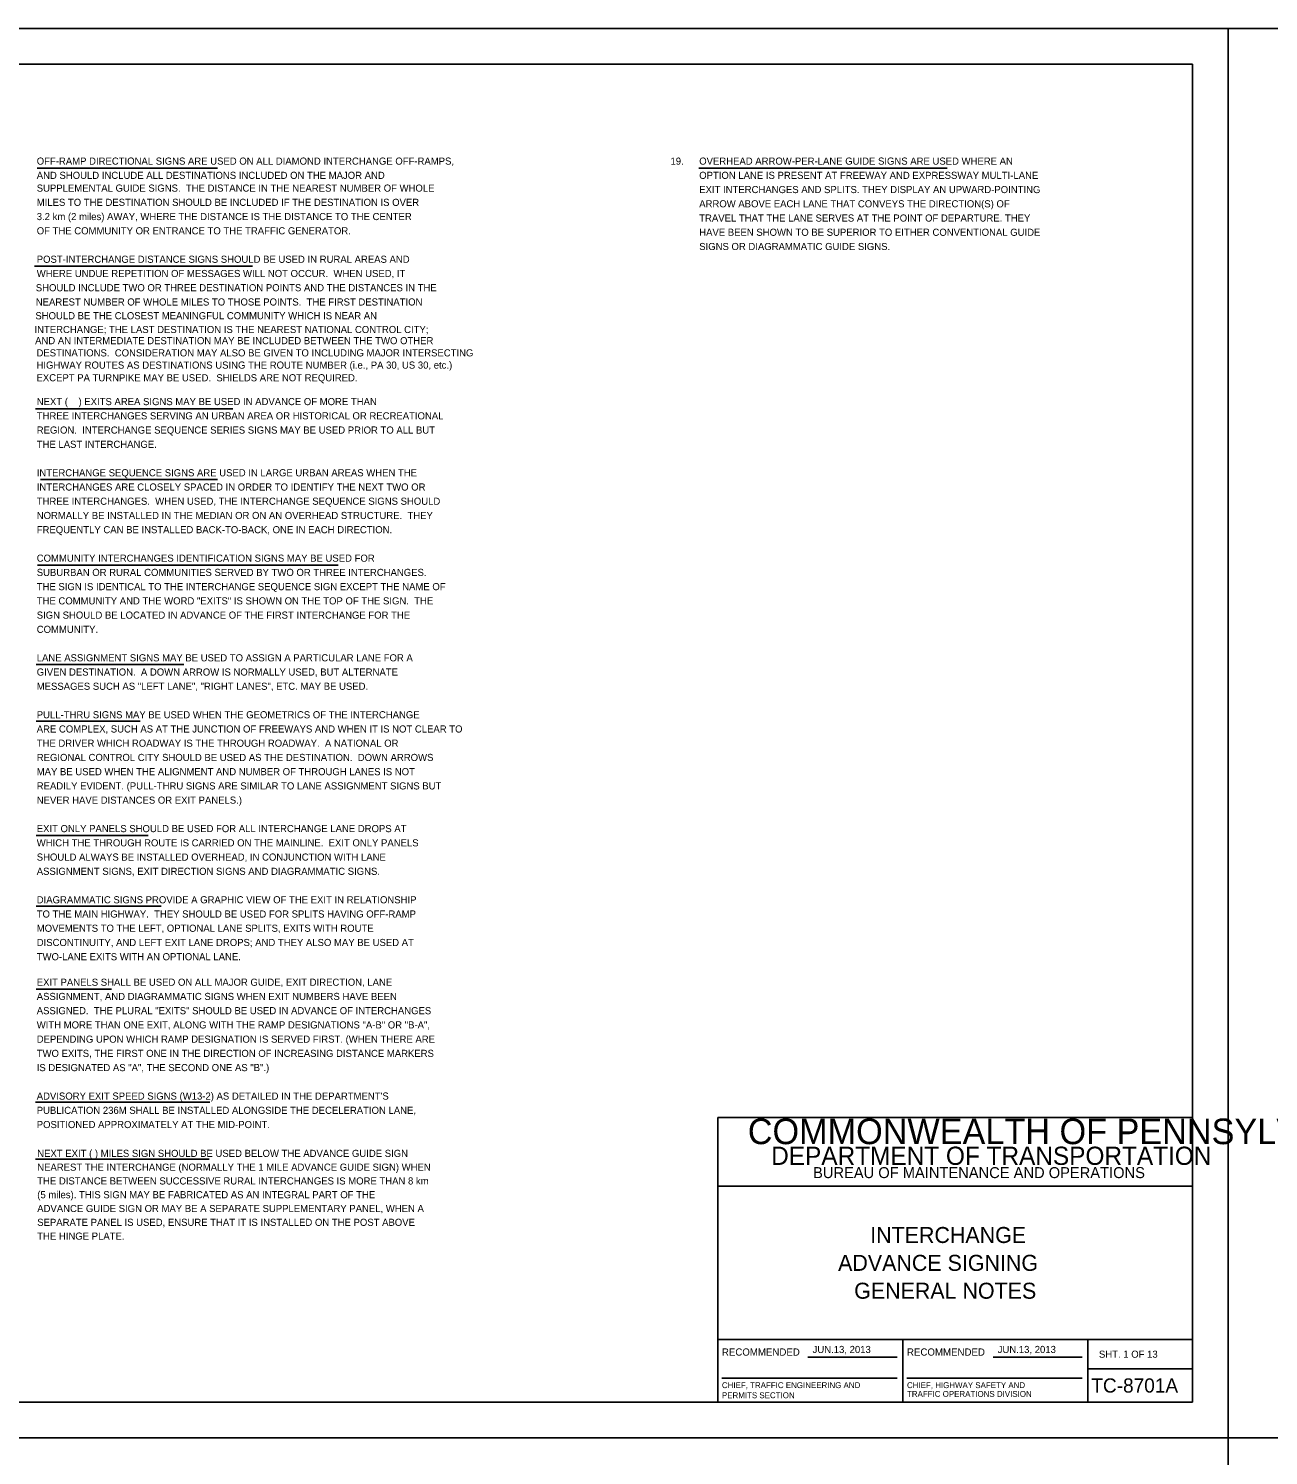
# Model space of a CAD drawing. Extents: x 644898 to 648326, y 298294 to 300670.
# Drawn here: x 645234 to 645756, y 300069 to 300670 of the extents above; entities that cross this region are included whole.
import ezdxf

# ---------------------------------------------------------------- set-up
doc = ezdxf.new("R2010")
doc.units = 0
for name, color, linetype in [('1', 7, 'Continuous'), ('2', 7, 'Continuous'), ('XCS-GRID-MIN', 7, 'Continuous')]:
    doc.layers.add(name, color=color, linetype=linetype)

msp = doc.modelspace()

# ---------------------------------------------------------------- linework, layer by layer
at = {"layer": '1'}
for p, q in [((644938.32, 300655.49), (645724.32, 300655.49)), ((645724.32, 300091.49), (645724.32, 300655.49)), ((645524.32, 300091.49), (645524.32, 300211.49)), ((645524.32, 300211.49), (645724.32, 300211.49)), ((645724.32, 300182.49), (645524.32, 300182.49)), ((645524.32, 300117.87), (645724.32, 300117.87)), ((645602.32, 300117.87), (645602.32, 300091.49)), ((645680.2, 300091.49), (645680.2, 300117.87)), ((645562.26, 300110.44), (645599.88, 300110.44)), ((645640.26, 300110.44), (645677.88, 300110.44)), ((645526.01, 300101.54), (645599.88, 300101.54)), ((645604.01, 300101.54), (645677.88, 300101.54)), ((645680.2, 300105.49), (645724.32, 300105.49)), ((645724.32, 300091.49), (644938.32, 300091.49)), ((644938.32, 300091.49), (645524.32, 300091.49))]:
    msp.add_line(p, q, dxfattribs=at)
at = {"layer": '2'}
for p, q in [((645237.5, 300611.62), (645313.5, 300611.62)), ((645516.22, 300611.63), (645620.93, 300611.63)), ((645236.37, 300570.37), (645328.25, 300570.37)), ((645236.75, 300510.24), (645319.87, 300510.24)), ((645238.87, 300480.37), (645313.5, 300480.37)), ((645237.62, 300444.24), (645364.25, 300444.24)), ((645237, 300402.37), (645299.25, 300402.37)), ((645237, 300378.49), (645280.87, 300378.49)), ((645237, 300330.37), (645284.25, 300330.37)), ((645237, 300300.49), (645289.62, 300300.49)), ((645237, 300265.62), (645268.75, 300265.62)), ((645236.75, 300217.87), (645310.25, 300217.87)), ((645236.75, 300193.87), (645309.88, 300193.87))]:
    msp.add_line(p, q, dxfattribs=at)
at = {"layer": 'XCS-GRID-MIN'}
for points in [[(644898.32, 300670.49), (645739.32, 300670.49), (645739.32, 300076.49), (644898.32, 300076.49)], [(645739.32, 300670.49), (646580.32, 300670.49), (646580.32, 300076.49), (645739.32, 300076.49)], [(644898.32, 300076.49), (645739.32, 300076.49), (645739.32, 299482.49), (644898.32, 299482.49)], [(645739.32, 300076.49), (646580.32, 300076.49), (646580.32, 299482.49), (645739.32, 299482.49)]]:
    msp.add_lwpolyline(points, close=True, dxfattribs=at)

# ---------------------------------------------------------------- texts
at = {"layer": '1'}
for s, height, p in [('COMMONWEALTH OF PENNSYLVANIA', 10.7828, (645536.92, 300200.22)), ('DEPARTMENT OF TRANSPORTATION', 7.6837, (645546.78, 300191.48)), ('BUREAU OF MAINTENANCE AND OPERATIONS', 4.6253, (645564.42, 300185.91)), ('INTERCHANGE', 6.75, (645588.5, 300158.56)), ('ADVANCE SIGNING', 6.75, (645574.97, 300146.81)), ('GENERAL NOTES', 6.75, (645581.75, 300135.06)), ('RECOMMENDED', 3.048, (645526.01, 300111.07)), ('RECOMMENDED', 3.048, (645604.01, 300111.07)), ('SHT. 1 OF 13', 3, (645684.91, 300110.18)), ('TC-8701A', 6, (645681.69, 300095.49)), ('CHIEF, TRAFFIC ENGINEERING AND', 2.5, (645526.01, 300097.38)), ('PERMITS SECTION', 2.5, (645526.01, 300093.13)), ('TRAFFIC OPERATIONS DIVISION', 2.5, (645604.01, 300093.68)), ('CHIEF, HIGHWAY SAFETY AND', 2.5, (645604.01, 300097.38))]:
    msp.add_text(s, height=height, dxfattribs=at).set_placement(p)
at = {"layer": '2'}
for s, p in [('OFF-RAMP DIRECTIONAL SIGNS ARE USED ON ALL DIAMOND INTERCHANGE OFF-RAMPS,', (645237.25, 300613.12)), ('19.', (645504.34, 300613.11)), ('OVERHEAD ARROW-PER-LANE GUIDE SIGNS ARE USED WHERE AN ', (645516.45, 300613.12)), ('AND SHOULD INCLUDE ALL DESTINATIONS INCLUDED ON THE MAJOR AND', (645237.25, 300607.12)), ('OPTION LANE IS PRESENT AT FREEWAY AND EXPRESSWAY MULTI-LANE', (645516.45, 300607.12)), ('SUPPLEMENTAL GUIDE SIGNS.  THE DISTANCE IN THE NEAREST NUMBER OF WHOLE', (645237.25, 300601.74)), ('EXIT INTERCHANGES AND SPLITS. THEY DISPLAY AN UPWARD-POINTING', (645516.45, 300601.12)), ('MILES TO THE DESTINATION SHOULD BE INCLUDED IF THE DESTINATION IS OVER ', (645237.25, 300595.74)), ('ARROW ABOVE EACH LANE THAT CONVEYS THE DIRECTION(S) OF', (645516.45, 300595.12)), ('3.2 km (2 miles) AWAY, WHERE THE DISTANCE IS THE DISTANCE TO THE CENTER ', (645237.25, 300589.74)), ('TRAVEL THAT THE LANE SERVES AT THE POINT OF DEPARTURE. THEY', (645516.45, 300589.12)), ('OF THE COMMUNITY OR ENTRANCE TO THE TRAFFIC GENERATOR.', (645237.25, 300583.74)), ('HAVE BEEN SHOWN TO BE SUPERIOR TO EITHER CONVENTIONAL GUIDE', (645516.45, 300583.12)), ('SIGNS OR DIAGRAMMATIC GUIDE SIGNS.', (645516.45, 300577.12)), ('POST-INTERCHANGE DISTANCE SIGNS SHOULD BE USED IN RURAL AREAS AND', (645237.25, 300571.74)), ('WHERE UNDUE REPETITION OF MESSAGES WILL NOT OCCUR.  WHEN USED, IT', (645237.25, 300565.74)), ('SHOULD INCLUDE TWO OR THREE DESTINATION POINTS AND THE DISTANCES IN THE', (645236.86, 300559.74)), ('NEAREST NUMBER OF WHOLE MILES TO THOSE POINTS.  THE FIRST DESTINATION', (645236.86, 300553.74)), ('SHOULD BE THE CLOSEST MEANINGFUL COMMUNITY WHICH IS NEAR AN', (645236.67, 300547.94)), ('AND AN INTERMEDIATE DESTINATION MAY BE INCLUDED BETWEEN THE TWO OTHER', (645236.57, 300537.42)), ('INTERCHANGE; THE LAST DESTINATION IS THE NEAREST NATIONAL CONTROL CITY;', (645236.28, 300542.13)), ('DESTINATIONS.  CONSIDERATION MAY ALSO BE GIVEN TO INCLUDING MAJOR INTERSECTING', (645237.15, 300532.28)), ('HIGHWAY ROUTES AS DESTINATIONS USING THE ROUTE NUMBER (i.e., PA 30, US 30, etc.)', (645237.15, 300527.13)), ('EXCEPT PA TURNPIKE MAY BE USED.  SHIELDS ARE NOT REQUIRED.', (645237.15, 300521.79)), ('NEXT (    ) EXITS AREA SIGNS MAY BE USED IN ADVANCE OF MORE THAN', (645237.25, 300511.74)), ('THREE INTERCHANGES SERVING AN URBAN AREA OR HISTORICAL OR RECREATIONAL', (645237.25, 300505.74)), ('REGION.  INTERCHANGE SEQUENCE SERIES SIGNS MAY BE USED PRIOR TO ALL BUT', (645237.25, 300499.74)), ('THE LAST INTERCHANGE.', (645237.25, 300493.74)), ('INTERCHANGE SEQUENCE SIGNS ARE USED IN LARGE URBAN AREAS WHEN THE', (645237.25, 300481.74)), ('INTERCHANGES ARE CLOSELY SPACED IN ORDER TO IDENTIFY THE NEXT TWO OR', (645237.25, 300475.74)), ('THREE INTERCHANGES.  WHEN USED, THE INTERCHANGE SEQUENCE SIGNS SHOULD', (645237.25, 300469.74)), ('NORMALLY BE INSTALLED IN THE MEDIAN OR ON AN OVERHEAD STRUCTURE.  THEY', (645237.25, 300463.74)), ('FREQUENTLY CAN BE INSTALLED BACK-TO-BACK, ONE IN EACH DIRECTION.', (645237.25, 300457.74)), ('COMMUNITY INTERCHANGES IDENTIFICATION SIGNS MAY BE USED FOR', (645237.25, 300445.74)), ('SUBURBAN OR RURAL COMMUNITIES SERVED BY TWO OR THREE INTERCHANGES. ', (645237.25, 300439.74)), ('THE SIGN IS IDENTICAL TO THE INTERCHANGE SEQUENCE SIGN EXCEPT THE NAME OF', (645237.25, 300433.74)), ('THE COMMUNITY AND THE WORD "EXITS" IS SHOWN ON THE TOP OF THE SIGN.  THE', (645237.25, 300427.74)), ('SIGN SHOULD BE LOCATED IN ADVANCE OF THE FIRST INTERCHANGE FOR THE', (645237.25, 300421.74)), ('COMMUNITY.', (645237.25, 300415.74)), ('LANE ASSIGNMENT SIGNS MAY BE USED TO ASSIGN A PARTICULAR LANE FOR A', (645237.25, 300403.74)), ('GIVEN DESTINATION.  A DOWN ARROW IS NORMALLY USED, BUT ALTERNATE', (645237.25, 300397.74)), ('MESSAGES SUCH AS "LEFT LANE", "RIGHT LANES", ETC. MAY BE USED.', (645237.25, 300391.74)), ('PULL-THRU SIGNS MAY BE USED WHEN THE GEOMETRICS OF THE INTERCHANGE', (645237.25, 300379.74)), ('ARE COMPLEX, SUCH AS AT THE JUNCTION OF FREEWAYS AND WHEN IT IS NOT CLEAR TO', (645237.25, 300373.74)), ('THE DRIVER WHICH ROADWAY IS THE THROUGH ROADWAY.  A NATIONAL OR', (645237.25, 300367.74)), ('REGIONAL CONTROL CITY SHOULD BE USED AS THE DESTINATION.  DOWN ARROWS', (645237.25, 300361.74)), ('MAY BE USED WHEN THE ALIGNMENT AND NUMBER OF THROUGH LANES IS NOT', (645237.25, 300355.74)), ('READILY EVIDENT. (PULL-THRU SIGNS ARE SIMILAR TO LANE ASSIGNMENT SIGNS BUT', (645237.25, 300349.74)), ('NEVER HAVE DISTANCES OR EXIT PANELS.)', (645237.25, 300343.74)), ('EXIT ONLY PANELS SHOULD BE USED FOR ALL INTERCHANGE LANE DROPS AT', (645237.25, 300331.74)), ('WHICH THE THROUGH ROUTE IS CARRIED ON THE MAINLINE.  EXIT ONLY PANELS', (645237.25, 300325.74)), ('SHOULD ALWAYS BE INSTALLED OVERHEAD, IN CONJUNCTION WITH LANE', (645237.25, 300319.74)), ('ASSIGNMENT SIGNS, EXIT DIRECTION SIGNS AND DIAGRAMMATIC SIGNS.', (645237.25, 300313.74)), ('DIAGRAMMATIC SIGNS PROVIDE A GRAPHIC VIEW OF THE EXIT IN RELATIONSHIP', (645237.25, 300301.74)), ('TO THE MAIN HIGHWAY.  THEY SHOULD BE USED FOR SPLITS HAVING OFF-RAMP', (645237.25, 300295.74)), ('MOVEMENTS TO THE LEFT, OPTIONAL LANE SPLITS, EXITS WITH ROUTE', (645237.25, 300289.74)), ('DISCONTINUITY, AND LEFT EXIT LANE DROPS; AND THEY ALSO MAY BE USED AT', (645237.25, 300283.74)), ('TWO-LANE EXITS WITH AN OPTIONAL LANE. ', (645237.25, 300277.74)), ('EXIT PANELS SHALL BE USED ON ALL MAJOR GUIDE, EXIT DIRECTION, LANE', (645237.25, 300266.99)), ('ASSIGNMENT, AND DIAGRAMMATIC SIGNS WHEN EXIT NUMBERS HAVE BEEN', (645237.25, 300260.99)), ('ASSIGNED.  THE PLURAL "EXITS" SHOULD BE USED IN ADVANCE OF INTERCHANGES', (645237.25, 300254.99)), ('WITH MORE THAN ONE EXIT, ALONG WITH THE RAMP DESIGNATIONS "A-B" OR "B-A",', (645237.25, 300248.99)), ('DEPENDING UPON WHICH RAMP DESIGNATION IS SERVED FIRST. (WHEN THERE ARE', (645237.25, 300242.99)), ('TWO EXITS, THE FIRST ONE IN THE DIRECTION OF INCREASING DISTANCE MARKERS', (645237.25, 300236.99)), ('IS DESIGNATED AS "A", THE SECOND ONE AS "B".)', (645237.25, 300230.99)), ("ADVISORY EXIT SPEED SIGNS (W13-2) AS DETAILED IN THE DEPARTMENT'S", (645237.25, 300218.99)), ('PUBLICATION 236M SHALL BE INSTALLED ALONGSIDE THE DECELERATION LANE,', (645237.25, 300212.99)), ('POSITIONED APPROXIMATELY AT THE MID-POINT.', (645237.25, 300206.99)), ('NEXT EXIT ( ) MILES SIGN SHOULD BE USED BELOW THE ADVANCE GUIDE SIGN', (645237.46, 300194.84)), ('NEAREST THE INTERCHANGE (NORMALLY THE 1 MILE ADVANCE GUIDE SIGN) WHEN', (645237.46, 300189.03)), ('THE DISTANCE BETWEEN SUCCESSIVE RURAL INTERCHANGES IS MORE THAN 8 km', (645237.46, 300183.22)), ('(5 miles). THIS SIGN MAY BE FABRICATED AS AN INTEGRAL PART OF THE ', (645237.46, 300177.41)), ('ADVANCE GUIDE SIGN OR MAY BE A SEPARATE SUPPLEMENTARY PANEL, WHEN A ', (645237.46, 300171.59)), ('SEPARATE PANEL IS USED, ENSURE THAT IT IS INSTALLED ON THE POST ABOVE ', (645237.46, 300165.78)), ('THE HINGE PLATE.', (645237.46, 300159.97)), ('JUN.13, 2013', (645564.23, 300112.18)), ('JUN.13, 2013', (645642.23, 300112.18))]:
    msp.add_text(s, height=3, dxfattribs=at).set_placement(p)

doc.saveas('drawing.dxf')
